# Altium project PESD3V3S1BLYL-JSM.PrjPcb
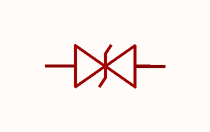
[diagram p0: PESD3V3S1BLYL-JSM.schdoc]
1 sheet, 1 parts. Net scope: global (net labels, ports and power ports of the same name join across sheets).

## Sheet PESD3V3S1BLYL-JSM.schdoc
size 127 x 101 mm

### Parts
D?  pesd3v3s1blyl-jsm  [DFN1006-2L-BI-1]  (value not drawn)

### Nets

Not connected (* = marked no-connect by the designer): D? 1 2

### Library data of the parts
D? = pesd3v3s1blyl-jsm: 极性:-;反向工作电压(Vrwm):3.3V;钳位电压:21V;峰值脉冲电流(Ipp):-;峰值脉冲功率(Ppp):84W@8/20us;击穿电压(VBR):4.2V;; Manufacturer: JSMSEMI(杰盛微); AddInBom: yes; ModelId: 4f73e746f3be4d299816d29f03249d6e; ModelTransform: 40.1574,24.4094,0,0,0,0,0,0,0; Reverse Stand-Off Voltage (Vrwm): 3.3V; Clamping Voltage: 21V; Voltage - Breakdown: 4.2V; Reverse Leakage Current (Ir): 100nA; Number of Channels: 单路; level of protection: IEC 61000-4-4；IEC 61000-4-2; Type: TVS; Junction Capacitance: 0.25pF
